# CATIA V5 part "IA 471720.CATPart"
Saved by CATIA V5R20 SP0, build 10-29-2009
Part number: IA 471720
Revision: ANY
Definition: UNKNOWN
Nomenclature: IA 471720
Source: Unknown
Bounding box of the stored display mesh (mm): x -2.35 to 2.35, y -7.925 to 9.045, z -2.35 to 2.35
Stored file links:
  C:\Users\Utente\Desktop\IO LAVORO\3D X SITO CF\CUMSA\3D files FA\FA 084712-20\IA 471720.CATPart

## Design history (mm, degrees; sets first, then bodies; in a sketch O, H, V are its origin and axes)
Body1 "Cortar-Extruir3" (main body)
  Solid1: solid without history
